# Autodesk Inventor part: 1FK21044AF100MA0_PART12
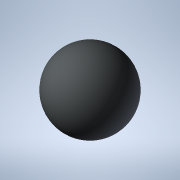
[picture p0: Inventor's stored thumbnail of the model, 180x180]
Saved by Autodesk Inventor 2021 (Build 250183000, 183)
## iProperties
Created: 2025-04
Part Number: 1FK21044AF100MA0_PART12
Material: Generic
Catalog Web Link: www.3dfindit.com
Description: -Servo synchronous motor
Document SubType Name: Modeling
Designer: psAdmin
Mass: 0.137258 g
Surface Area: 1.2868 cm^2
Volume: 0.137258 cm^3
Density: 1 g/cm^3
Appearance: PSOLRGB-212-217-219
Category: PARTsolutions
Title: 1FK21044AF100MA0_PART12
Author: Cadenas PARTsolutions
Comments: Servo synchronous motor
Sending System: PARTsolutions
Preprocessor: ST-DEVELOPER v19.3
PSOL_IDENT_0: {$CADENAS_DATA/23d-libs/siemens_ag/_cat_/ec/e4/1fk21044af100ma0.prj},216 {VTYP=3D},{NB=1FK21044AF100
PSOL_IDENT_1: MA0_PART12},{LINA=1FK21044AF100MA0_PART12},{NN=1FK21044AF100MA0_PART12},{NOPRJ=TRUE},{DATE=19.08.202
PSOL_IDENT_2: 5 14:01:05},{GEOMDATE=30.07.2025 02:01:01},{VERSION=},{LINEID=10},{WBVAR=},{WBNUMERIC=}  {NB=1FK2104
PSOL_IDENT_3: 4AF100MA0_PART12},{LINA=1FK21044AF100MA0_PART12},{KT=DUMMY},{PREVIEW=../../../_pool_/cb/72/p_d211_xx
PSOL_IDENT_4: _00434j.png},{DESCSHORT=SIMOTICS S-1FK2 HD, SINAMICS S210 3AC 400V-480V, 1.27 Nm, 3000 rpm},{DESCLON
PSOL_IDENT_5: G=SIMOTICS S-1FK2 HD servo motor M0=1.27 Nm; PN = 0.4 kW at nN=3000 rpm (380-480 V); PN = 0.2 kW at
PSOL_IDENT_6: nN=1500 rpm (200-240 V); with holding brake; degree of protection IP64; cylindrical shaft D19x40mm;
PSOL_IDENT_7: absolute encoder 22-bit + 12-bit multiturn (encoder AM22DQC); with OCC interface; plug size M17, rot
PSOL_IDENT_8: atable; SIMOTICS S-1FK2 servomotorfor a wide range of uses in industrial environments. SIMOTICS S‑1F
PSOL_IDENT_9: K2 servomotors are compact synchronous motors with a high dynamic performance that set themselves ap
PSOL_IDENT_10: art as a result of their high power density, degree of protection and overload capability. The motor
PSOL_IDENT_11: s are available in two variants: as High Dynamic variant (highest dynamic performance as a result of
PSOL_IDENT_12: the low intrinsic moment of inertia for applications demanding a high dynamic performance with low
PSOL_IDENT_13: moved masses) - and as Compact variant (precise and stable closed-loop control for medium up to larg
PSOL_IDENT_14: e moved masses as a result of a medium intrinsic moment of inertia). SIMOTICSS‑1FK2 servomotors full
PSOL_IDENT_15: y exploit their strengths in a system with the SINAMICSS210 frequency converter and simple connectio
PSOL_IDENT_16: n using the one cable connection (OCC). Advantages include the short control and positioning times,
PSOL_IDENT_17: fast and precise correction of disturbing quantities as well as stable control with a high dynamic p
PSOL_IDENT_18: erformance. The servo motors can be configured to address a wide range of requirements. For example
PSOL_IDENT_19: with and without holding brake, IP64 or IP65 degree of protection, singleturn or multiturn absolute
PSOL_IDENT_20: encoders - to name just a few. Further, the servomotors are available in different shaft heights ext
PSOL_IDENT_21: ending from 20 to 100. A shaft sealing ring is available to achieve an IP65 degree of protection and
PSOL_IDENT_22: for subsequent mounting at the motor or as spare part. SIMOTICS - the optimum motor for each and ev
PSOL_IDENT_23: ery motion control application.},{INTNO=195125043275},{SUPPLIERALTNO=1FK2104-4AF10-0MA0},{MANUID=1FK
PSOL_IDENT_24: 21044AF100MA0},{MANUNAME=Siemens},{MANUTYPEDESC=Synchronous motor 1FK2-HD 1.27 NM},{AAU732=SIMOTICS}
PSOL_IDENT_25: ,{AAO057=S-1FK2},{AAU734=SIMOTICS S-1FK2 HD servo motor M0=1.27 Nm; PN = 0.4 kW at nN=3000 rpm (380-
PSOL_IDENT_26: 480 V); PN = 0.2 kW at nN=1500 rpm (200-240 V); with holding brake; degree of protection IP64; cylin
PSOL_IDENT_27: drical shaft D19x40mm; absolute encoder 22-bit + 12-bit multiturn (encoder AM22DQC); with OCC interf
PSOL_IDENT_28: ace; plug size M17, rotatable;},{AAW338=Synchronous motor 1FK2-HD 1.27 NM},{AAO742=SIMOTICS},{AAO663=
PSOL_IDENT_29: 4042948694015},{NOCUPEROU=1},{PRICEQUANTITY=1},{QUANTITYMIN=1},{QUANTITYINT=1},{CTN=85015100},{COO=D
PSOL_IDENT_30: E},{AAO676=1FK2104-4AF10-0MA0},{AAO677=Siemens AG},{ORDERUNIT=C62},{CONTENTUNIT=C62}
NB: 1FK21044AF100MA0_PART12
NT: Servo synchronous motor
NBSYN: $MANUID._PART12
LINA: 1FK21044AF100MA0_PART12
CATALOG: SIEMENS
PREVIEW: ../../../_pool_/cb/72/p_d211_xx_00434j.png
DESCSHORT: SIMOTICS S-1FK2 HD, SINAMICS S210 3AC 400V-480V, 1.27 Nm, 3000 rpm
DESCLONG: SIMOTICS S-1FK2 HD servo motor M0=1.27 Nm; PN = 0.4 kW at nN=3000 rpm (380-480 V); PN = 0.2 kW at nN=1500 rpm (200-240 V); with holding brake; degree of protect
INTNO: 195125043275
SUPPLIERALTNO: 1FK2104-4AF10-0MA0
MANUID: 1FK21044AF100MA0
MANUNAME: Siemens
MANUTYPEDESC: Synchronous motor 1FK2-HD 1.27 NM
AAU732: SIMOTICS
AAO057: S-1FK2
AAU734: SIMOTICS S-1FK2 HD servo motor M0=1.27 Nm; PN = 0.4 kW at nN=3000 rpm (380-480 V); PN = 0.2 kW at nN=1500 rpm (200-240 V); with holding brake; degree of protect
AAW338: Synchronous motor 1FK2-HD 1.27 NM
AAO742: SIMOTICS
AAO663: 4042948694015.0
NOCUPEROU: 1
PRICEQUANTITY: 1
QUANTITYMIN: 1
QUANTITYINT: 1
CTN: 85015100
COO: DE
ARTICLENO: 1FK21044AF100MA0_PART12
BOMINFO: 1FK21044AF100MA0_PART12
CREATOR: CADENAS GmbH
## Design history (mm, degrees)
feature "2025_04_17_15_33_01_0673"
body "Solid1"
